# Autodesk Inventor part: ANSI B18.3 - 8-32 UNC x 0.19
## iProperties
IsCustomPart: 0
Created: 2008-02
Part Number: ANSI B18.3 - 8-32 UNC x 0.19
Material: Steel, Mild
Description: Hexagon Socket Set Screw - Flat Point
Document SubType Name: Modeling
Standard: ANSI B18.3
Standard Revision: 2003
Standards Organization: ANSI
Language: en-US
Size Designation: 8-32 UNC x 0.19
Categories: <MemberInstance><Categories><Category DisplayName="Fasteners" InternalName="e4da775c-781d-43d5-af7c-5136215cf5a6" Mnemonic="FSTN"><Category DisplayName="Bolts"
Density: 1 g/cm^3
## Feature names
1. Body [Revolution]
2. Chamfer1
3. Slot [Extrusion]
4. Chamfer2
